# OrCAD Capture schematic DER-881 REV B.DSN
size Custom; title: DER-881; rev: B
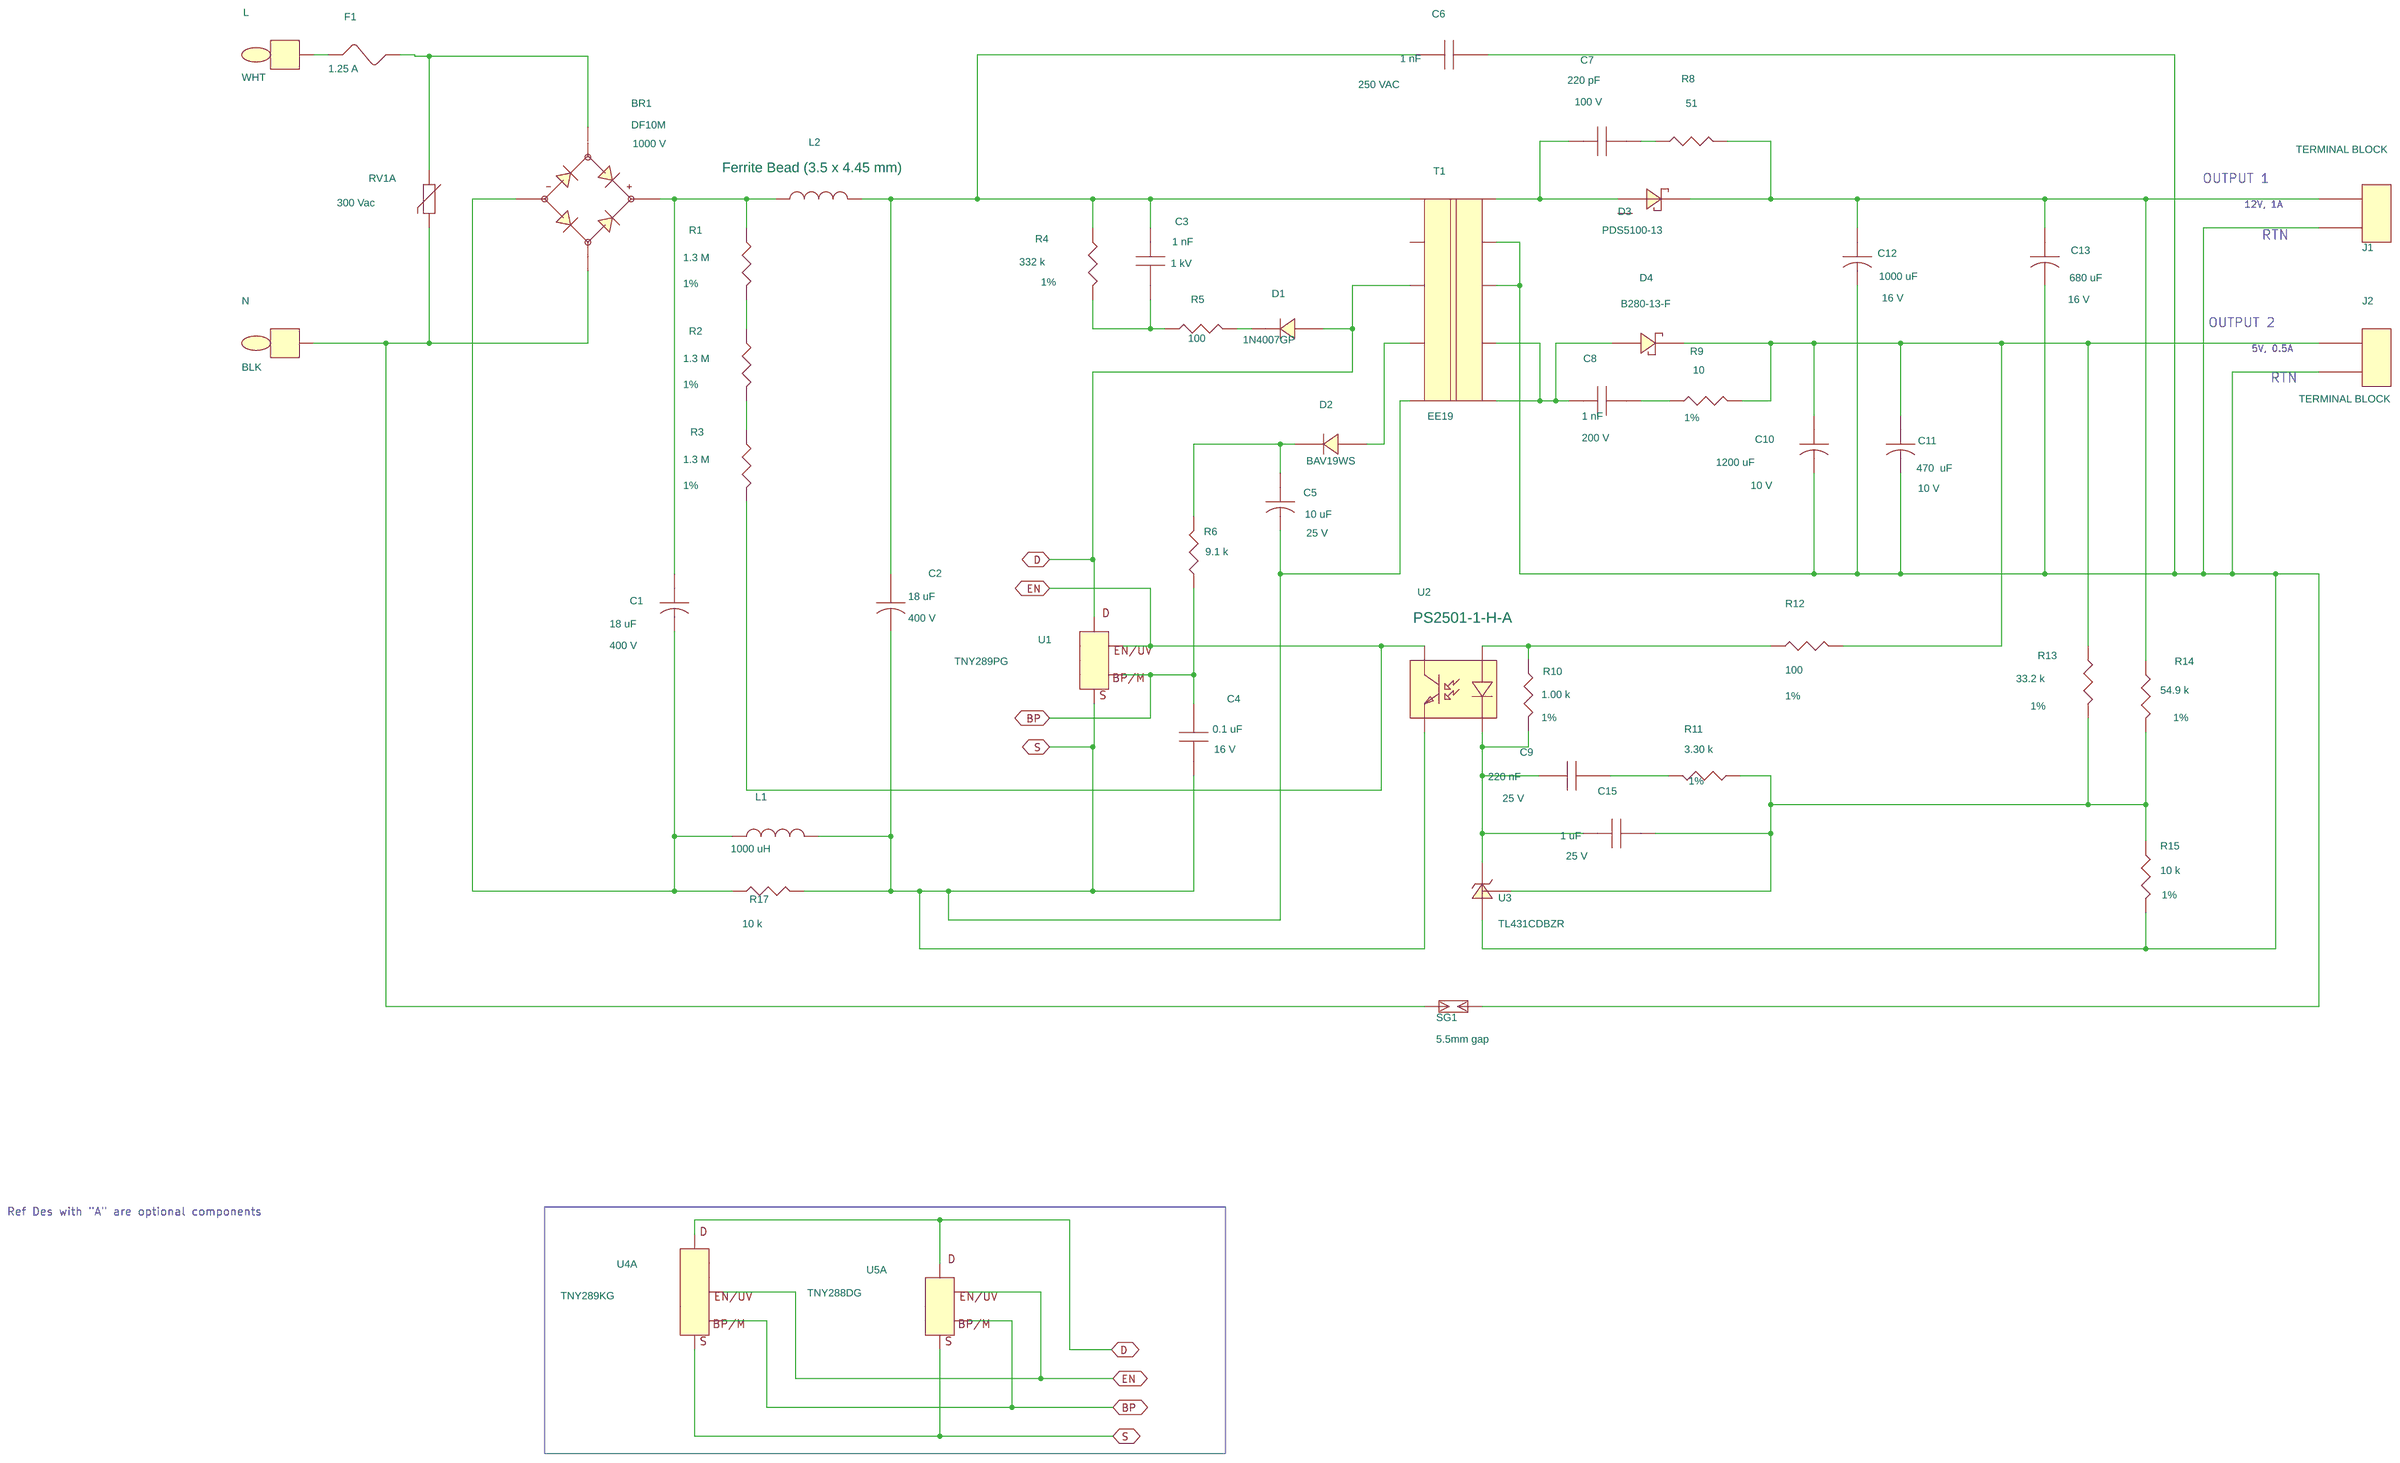
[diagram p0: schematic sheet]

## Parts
BR1  DF10M  [pi_4-edip]
C1  18 uF  [pipolcapcyld400ls200040]
C2  18 uF  [pipolcapcyld400ls200040]
C3  1 nF  [pi_np_cap300x250ls200d030]
C4  0.1 uF  [pismc0805]
C5  10 uF  [pipolcapclyd200ls80030]
C6  1 nF  [pinpycaprad540x290ls400040]
C7  220 pF  [pismc0805]
C8  1 nF  [pismc0805]
C9  220 nF  [pismc0805]
C10  1200 uF  [pipolcapcyld400ls200040]
C11  470  uF  [pipolcapclyd320ls140030]
C12  1000 uF  [pipolcapcyld400ls200040]
C13  680 uF  [pipolcapclyd320ls140030]
C15  1 uF  [pismc0805]
D1  1N4007GP  [pidv200x110x040do41]
D2  BAV19WS  [pismsod323]
D3  PDS5100-13  [pismdpowerdi5]
D4  B280-13-F  [pismsmb]
F1  1.25 A  [pi_rst_microfuse]
J1  TERMINAL BLOCK  [pi_term_block_2pin_ls200]
J2  TERMINAL BLOCK  [pi_term_block_2pin_ls200]
L  WHT  [pitpkeystone125x125]
L1  1000 uH  [pichoketokinvd345h453ls197d030]
L2  Ferrite Bead (3.5 x 4.45 mm)  [pi12wresd180ls675d040]
N  BLK  [pitpkeystone125x125]
R1  1.3 M  [pismr0805]
R2  1.3 M  [pismr0805]
R3  1.3 M  [pismr0805]
R4  332 k  [pismr1206]
R5  100  [pismr1206]
R6  9.1 k  [pismr0805]
R8  51  [pismr1206]
R9  10  [pismr1206]
R10  1.00 k  [pismr0805]
R11  3.30 k  [pismr0805]
R12  100  [pismr1206]
R13  33.2 k  [pismr0805]
R14  54.9 k  [pismr0805]
R15  10 k  [pismr0805]
R17  10 k  [pismr1206]
RV1A  300 Vac  [pidisc350x225ls240x140040]
SG1  5.5mm gap  [PI_SPARK_GAP_5p5MM]
T1  EE19  [pi_bobbin_ee19_tf-1932_10p]
U1  TNY289PG  [piicdip8cshort5678]
U2  PS2501-1-H-A  [pi_dip4]
U3  TL431CDBZR  [pismsot23123_1]
U4A  TNY289KG  [pi_smd_esop_11-12p_short7-11]
U5A  TNY288DG  [pismso8dnshort5678]

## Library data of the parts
BR1 = DIODE_BRIDGE_+-~~: Disp_Voltage: 1000 V; Part Number: 15-00903-00
C1 C2 = CAP_POL: ALT_SYMBOLS: pipolcapclyd395x630ls200030h; Disp_Voltage: 400 V; FPLIST: pipolcapcyld400ls200040,pipolcapclyd395x630ls200030h; Part Number: 20-09063-00; Voltage: 400 V
C3 = CAP_NP: Disp_Voltage: 1 kV; Part Number: 20-00947-00; Voltage: 1 kV
C4 = CAP_NP: Disp_Voltage: 16 V; Part Number: 20-09164-00; Voltage: 16 V
C5 = CAP_POL: ALT_SYMBOLS: pipolcapclyd200ls80030h; Disp_Voltage: 25 V; FPLIST: pipolcapclyd200ls80030,pipolcapclyd200ls80030h; Part Number: 20-01182-00; Voltage: 25 V
C6 = CAP_NP: ALT_SYMBOLS: pinpycaprad540x290ls400040h,pinpycaprad500x220ls400040; Disp_Voltage: 250 VAC; FPLIST: pinpycaprad540x290ls400040,pinpycaprad540x290ls400040h,pinpycaprad500x220ls400040; Part Number: 20-00375-00; Voltage: 250 VAC
C7 = CAP_NP: Disp_Voltage: 100 V; Part Number: 20-00580-00; Voltage: 100 V
C8 = CAP_NP: ALT_SYMBOLS: pismc0805_1; Disp_Voltage: 200 V; FPLIST: pismc0805,pismc0805_1; Part Number: 20-00737-00; Voltage: 200 V
C9 = CAP_NP: Disp_Voltage: 25 V; Part Number: 20-00237-00; Voltage: 25 V
C10 = CAP_POL: ALT_SYMBOLS: pipolcapcyld400ls200040800h; Disp_Voltage: 10 V; FPLIST: pipolcapcyld400ls200040,pipolcapcyld400ls200040800h; Part Number: 20-00008-00; Voltage: 10 V
C11 = CAP_POL: ALT_SYMBOLS: pipolcapclyd320ls140030430h; Disp_Voltage: 10 V; FPLIST: pipolcapclyd320ls140030,pipolcapclyd320ls140030430h,pipolcapclyd320ls140030430h; Part Number: 20-00003-00; Voltage: 10 V
C12 = CAP_POL: ALT_SYMBOLS: pipolcapcyld400ls200040800h; Disp_Voltage: 16 V; FPLIST: pipolcapcyld400ls200040,pipolcapcyld400ls200040800h; Part Number: 20-00019-00; Voltage: 16 V
C13 = CAP_POL: ALT_SYMBOLS: pipolcapclyd320ls140d30h750; Disp_Voltage: 16 V; FPLIST: pipolcapclyd320ls140030,pipolcapclyd320ls140d30h750; Part Number: 20-00016-00; Voltage: 16 V
C15 = CAP_NP: Disp_Voltage: 25 V; Part Number: 20-09171-00; Voltage: 25 V
D1 = DIODE: ALT_SYMBOLS: pidax475x125040do41,pidv200x110x040do41wbead,pidax390x125040do41; FPLIST: pidv200x110x040do41,pidax475x125040do41,pidv200x110x040do41wbead,pidax390x125040do41; Part Number: 15-00293-00
D2 = DIODE: Part Number: 15-00658-00
D3 = DIODE_SCHOTTKY_PWRDI_AAC: Part Number: 15-01120-00
D4 = DIODE_SCHOTTKY: Part Number: 15-01294-00
F1 = FUSE: ALT_SYMBOLS: pirstmicrofusehoz; FPLIST: pi_rst_microfuse,pirstmicrofusehoz; Part Number: 40-00062-00
J1 J2 = CON2: Part Number: 35-00277-00
L = TESTPOINT: Part Number: 35-00044-00
L1 = INDUCTOR: Part Number: 30-00208-00
L2 = INDUCTOR: ALT_SYMBOLS: pi12wvresd180ls150d040,pi12wvresd180ls200d040,pi12wvresd180ls250d040; FPLIST: pi12wresd180ls675d040,pi12wvresd180ls150d040,pi12wvresd180ls200d040,pi12wvresd180ls250d040; Part Number: 30-00143-00
N = TESTPOINT: Part Number: 35-00042-00
R1-R3 = R: Disp_Tol: 1%; Part Number: 05-00879-00
R4 = R: Disp_Tol: 1%; Part Number: 05-00435-00
R5 = R: Part Number: 05-01328-00
R6 = R: Part Number: 05-01542-00
R8 = R: Part Number: 05-01321-00
R9 = R: Disp_Tol: 1%; Part Number: 05-00001-00
R10 = R: Disp_Tol: 1%; Part Number: 05-03310-00
R11 = R: Disp_Tol: 1%; Part Number: 05-05369-00
R12 = R: Disp_Tol: 1%; Part Number: 05-00097-00
R13 = R: Disp_Tol: 1%; Part Number: 05-00734-00
R14 = R: Disp_Tol: 1%; Part Number: 05-00755-00
R15 = R: Disp_Tol: 1%; Part Number: 05-00684-00
R17 = R: Part Number: 05-01376-00
RV1A = VARISTOR: Part Number: 85-00031-00
SG1 = SPARK_GAP: Part Number: 66-00357-00
T1 = BEE19_10P_GENERIC: Part Number: 25-00969-00
U1 = TNY_3: Part Number: 10-00539-00
U2 = OPTO_DIP: Part Number: 53-00010-00
U3 = TL431CDBZR: Part Number: 45-00492-00
U4A = DEV_TNY_3_eSOP: Part Number: 10-00540-00
U5A = TNY_3: Part Number: 10-00776-00

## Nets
BP: C4.1 R6.1 U1.2(BP/M) U4A.2(BP/M) U5A.2(BP/M)
D: D1.2 T1.3 U1.4(D) U4A.6(D) U5A.4(D)
EN: R3.2 U1.1(EN) U2.4(Collector) U4A.1(EN) U5A.1(EN)
NC3: U4A.3(NC3)
NC4: U4A.4(NC4)
S: C2.2 C4.2 C5.2 L1.2 R17.2 T1.5 U1.5(S) U2.3(E) U4A.7(S7) U5A.5(S)
SOURCE: U1.6(SOURCE) U1.7(SOURCE) U1.8(SOURCE) U4A.8(SOURCE) U4A.9(SOURCE) U4A.10(SOURCE) U4A.11(SOURCE) U4A.12(SOURCE) U5A.6(SOURCE) U5A.7(SOURCE) U5A.8(SOURCE)
N12060109: F1.1 L.1
N12060113: BR1.3 F1.2 RV1A.1
N12060137: C2.1 C3.1 C6.1 L2.2 R4.1 T1.1
N12060145: C6.2 C10.2 C11.2 C12.2 C13.2 J1.1 J2.2 R15.2 SG1.2 T1.8 T1.9 U3.3(A)
N12060209: C7.1 D3.1 T1.10
N12060217: C7.2 R8.1
N12060221: C12.1 C13.1 D3.2 J1.2 R8.2 R14.1
N12060293: BR1.2 C1.2 L1.1 R17.1
N12060301: BR1.1 C1.1 L2.1 R1.1
N12060425: BR1.4 N.1 RV1A.2 SG1.1
N12060595: R1.2 R2.1
N12060599: C3.2 R4.2 R5.1
N12060659: D1.1 R5.2
N12060735: D2.2 T1.4
N12060743: C8.1 D4.2 T1.6 T1.7
N12060759: C10.1 C11.1 D4.1 J2.1 R9.2 R12.2 R13.1
N12060853: R2.2 R3.1
N12060877: C8.2 R9.1
N12060987: C5.1 D2.1 R6.2
N12061297: R10.1 R12.1 U2.1(A)
N12061441: C9.1 C15.1 R10.2 U2.2(C) U3.1(C)
N12061445: C15.2 R11.1 R13.2 R14.2 R15.1 U3.2(VREF)
N12061535: C9.2 R11.2

Not connected (* = marked no-connect by the designer): D3 3; T1 2

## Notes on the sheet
- OUTPUT 1
- 12V, 1A
- RTN
- OUTPUT 2
- 5V, 0.5A
- RTN
- Ref Des with "A" are optional components
